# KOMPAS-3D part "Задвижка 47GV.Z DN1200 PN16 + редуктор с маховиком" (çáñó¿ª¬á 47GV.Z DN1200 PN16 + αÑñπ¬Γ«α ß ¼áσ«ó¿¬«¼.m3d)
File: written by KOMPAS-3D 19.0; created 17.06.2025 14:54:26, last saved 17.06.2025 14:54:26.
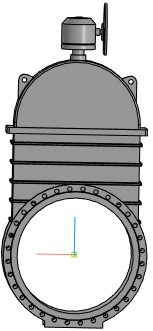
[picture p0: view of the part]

Document properties: Полное имя файла: Задвижка 47GV.Z DN1200 PN16 + редуктор с маховиком.a3d

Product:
- Part/product: Задвижка 47GV.Z DN1200 PN16 + редуктор с маховиком
    Масса: 6597.11

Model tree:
1. Операция без истории:1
